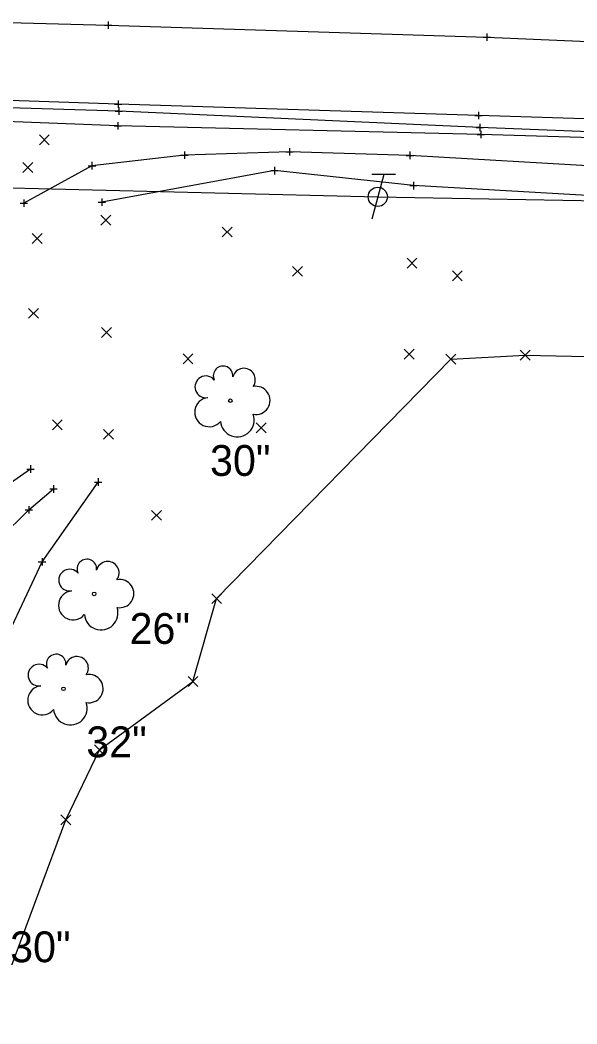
# Model space of a CAD drawing. Extents: x 2005176 to 2005823, y 572472 to 572942.
# Drawn here: x 2005564.6 to 2005639.9, y 572472.3 to 572608.1 of the extents above; entities that cross this region are included whole.
import ezdxf

# ---------------------------------------------------------------- set-up
doc = ezdxf.new("R2010")
doc.units = 0
for name, color, linetype in [('GE_X_Alignment_100_Bearings', 7, 'Continuous'), ('GE_X_Alignment_100_Cardinal_Points', 7, 'Continuous'), ('GE_X_Alignment_100_Distances', 7, 'Continuous'), ('GE_X_Alignment_100_Stations', 7, 'Continuous'), ('GE_X_Alignment_500_Bearings', 7, 'Continuous'), ('GE_X_Alignment_500_Cardinal_Points', 7, 'Continuous'), ('GE_X_Alignment_500_Distances', 7, 'Continuous'), ('SC_Scratch1', 7, 'Continuous'), ('SC_Scratch10', 7, 'Continuous'), ('SC_Scratch8', 7, 'Continuous'), ('SV_P_Mon_Cells_Set', 7, 'Continuous'), ('SV_X_Random_Point', 7, 'Continuous'), ('SV_X_Shot_Marker', 7, 'Continuous'), ('SV_X_Terrain_Boundary', 7, 'Continuous'), ('UT_X_Overhead_Telecom', 7, 'Continuous'), ('VG_X_Text', 7, 'Continuous')]:
    doc.layers.add(name, color=color, linetype=linetype)

msp = doc.modelspace()

# ---------------------------------------------------------------- linework, layer by layer
at = {"layer": 'GE_X_Alignment_100_Bearings'}
msp.add_lwpolyline([(2005818.64, 572588.97), (2005775.2, 572590.4), (2005728.29, 572591.88), (2005676.68, 572593.61), (2005626.55, 572595.19), (2005577.83, 572596.72), (2005526.97, 572598.44), (2005477.01, 572599.53), (2005423.67, 572600.7), (2005368.75, 572601.99), (2005321.74, 572602.99), (2005266.72, 572604.35), (2005220.03, 572605.66)], dxfattribs=at)
at = {"layer": 'GE_X_Alignment_100_Cardinal_Points'}
msp.add_lwpolyline([(2005220.5, 572615.99), (2005272.51, 572614.37), (2005322.2, 572613.2), (2005370.62, 572612.29), (2005424.94, 572611.27), (2005476.5, 572610.17), (2005524.32, 572608.79), (2005576.49, 572607.4), (2005627.69, 572605.77), (2005677.11, 572603.68), (2005728.03, 572601.92), (2005776.18, 572600.5), (2005820.14, 572599.28)], dxfattribs=at)
at = {"layer": 'GE_X_Alignment_100_Distances'}
msp.add_lwpolyline([(2005818.7, 572589.05), (2005775.2, 572590.4), (2005728.29, 572591.88), (2005676.68, 572593.61), (2005626.55, 572595.19), (2005577.83, 572596.72), (2005526.97, 572598.44), (2005477.01, 572599.53), (2005423.67, 572600.7), (2005368.75, 572601.99), (2005321.74, 572602.99), (2005266.72, 572604.35), (2005220.06, 572605.65)], dxfattribs=at)
at = {"layer": 'GE_X_Alignment_100_Stations'}
msp.add_lwpolyline([(2005818.32, 572583.75), (2005776.41, 572584.84), (2005733.38, 572587.41), (2005688.89, 572587.43), (2005643.67, 572588.24), (2005617.3, 572589.8), (2005601, 572590.26), (2005586.78, 572589.84), (2005574.29, 572588.4), (2005565.07, 572583.34)], dxfattribs=at)
at = {"layer": 'GE_X_Alignment_500_Bearings'}
for points in [[(2005565.96, 572547.38), (2005550.47, 572536.53), (2005541.81, 572523.07)], [(2005532.27, 572476.65), (2005533.84, 572485.17), (2005538.2, 572494.97), (2005543.28, 572506.2), (2005549.27, 572518.3), (2005553.94, 572530.22), (2005565.74, 572541.87), (2005569.09, 572544.68)]]:
    msp.add_lwpolyline(points, dxfattribs=at)
at = {"layer": 'GE_X_Alignment_500_Cardinal_Points'}
for points in [[(2005818.94, 572578.27), (2005776.52, 572579.63), (2005733.4, 572581.57), (2005688.76, 572580.93), (2005659.16, 572582.97), (2005643.63, 572584.23), (2005617.78, 572585.7), (2005598.98, 572587.73), (2005575.61, 572583.45)], [(2005556.42, 572509.95), (2005560.7, 572520.33), (2005567.53, 572534.83), (2005575.11, 572545.62)]]:
    msp.add_lwpolyline(points, dxfattribs=at)
at = {"layer": 'GE_X_Alignment_500_Distances'}
msp.add_lwpolyline([(2005220.4, 572616.04), (2005272.51, 572614.37), (2005322.2, 572613.2), (2005370.62, 572612.29), (2005424.94, 572611.27), (2005476.5, 572610.17), (2005524.32, 572608.79), (2005576.49, 572607.4), (2005627.69, 572605.77), (2005677.11, 572603.68), (2005728.03, 572601.92), (2005776.18, 572600.5), (2005820.14, 572599.26)], dxfattribs=at)
at = {"layer": 'SC_Scratch1'}
for p, q in [((2005615.34, 572587.19), (2005612.14, 572587.19)), ((2005613.74, 572587.19), (2005612.14, 572581.19))]:
    msp.add_line(p, q, dxfattribs=at)
msp.add_circle((2005612.94, 572584.19), 1.3, dxfattribs=at)
at = {"layer": 'SC_Scratch10'}
msp.add_lwpolyline([(2005818.55, 572585.94), (2005774.93, 572587.72), (2005728.19, 572589.23), (2005676.71, 572591.12), (2005626.89, 572592.62), (2005577.77, 572593.78), (2005527.62, 572595.75), (2005477.17, 572596.25), (2005467.62, 572596.6)], dxfattribs=at)
at = {"layer": 'SC_Scratch8'}
msp.add_lwpolyline([(2005818.66, 572586.64), (2005775.01, 572588.28), (2005728.16, 572589.79), (2005676.75, 572591.58), (2005626.73, 572593.57), (2005577.92, 572595.76), (2005527.42, 572597.32), (2005476.91, 572598.65), (2005423.43, 572599.27), (2005368.77, 572600.6), (2005321.59, 572601.67), (2005267.03, 572602.73), (2005220.03, 572603.93)], dxfattribs=at)
at = {"layer": 'SV_P_Mon_Cells_Set'}
for p, q in [((2005576.49, 572607.9), (2005576.49, 572606.9)), ((2005576.49, 572607.9), (2005576.49, 572606.9)), ((2005575.99, 572607.4), (2005576.99, 572607.4)), ((2005575.99, 572607.4), (2005576.99, 572607.4)), ((2005576.49, 572607.4), (2005576.49, 572607.4)), ((2005576.49, 572607.4), (2005576.49, 572607.4)), ((2005627.69, 572606.27), (2005627.69, 572605.27)), ((2005627.69, 572606.27), (2005627.69, 572605.27)), ((2005627.19, 572605.77), (2005628.19, 572605.77)), ((2005627.19, 572605.77), (2005628.19, 572605.77)), ((2005627.69, 572605.77), (2005627.69, 572605.77)), ((2005627.69, 572605.77), (2005627.69, 572605.77)), ((2005577.33, 572596.72), (2005578.33, 572596.72)), ((2005577.33, 572596.72), (2005578.33, 572596.72)), ((2005577.83, 572597.22), (2005577.83, 572596.22)), ((2005577.83, 572597.22), (2005577.83, 572596.22)), ((2005577.83, 572596.72), (2005577.83, 572596.72)), ((2005577.83, 572596.72), (2005577.83, 572596.72)), ((2005577.42, 572595.76), (2005578.42, 572595.76)), ((2005577.92, 572596.26), (2005577.92, 572595.26)), ((2005577.92, 572595.76), (2005577.92, 572595.76)), ((2005626.55, 572595.69), (2005626.55, 572594.69)), ((2005626.55, 572595.69), (2005626.55, 572594.69)), ((2005577.77, 572594.28), (2005577.77, 572593.28)), ((2005626.05, 572595.19), (2005627.05, 572595.19)), ((2005626.05, 572595.19), (2005627.05, 572595.19)), ((2005626.55, 572595.19), (2005626.55, 572595.19)), ((2005626.55, 572595.19), (2005626.55, 572595.19)), ((2005626.73, 572594.07), (2005626.73, 572593.07)), ((2005577.27, 572593.78), (2005578.27, 572593.78)), ((2005577.77, 572593.78), (2005577.77, 572593.78)), ((2005626.23, 572593.57), (2005627.23, 572593.57)), ((2005626.39, 572592.62), (2005627.39, 572592.62)), ((2005626.73, 572593.57), (2005626.73, 572593.57)), ((2005626.89, 572593.12), (2005626.89, 572592.12)), ((2005626.89, 572592.62), (2005626.89, 572592.62)), ((2005586.28, 572589.84), (2005587.28, 572589.84)), ((2005586.78, 572590.34), (2005586.78, 572589.34)), ((2005586.78, 572589.84), (2005586.78, 572589.84)), ((2005600.5, 572590.26), (2005601.5, 572590.26)), ((2005601, 572590.76), (2005601, 572589.76)), ((2005601, 572590.26), (2005601, 572590.26)), ((2005617.3, 572590.3), (2005617.3, 572589.3)), ((2005574.29, 572588.9), (2005574.29, 572587.9)), ((2005616.8, 572589.8), (2005617.8, 572589.8)), ((2005617.3, 572589.8), (2005617.3, 572589.8)), ((2005573.79, 572588.4), (2005574.79, 572588.4)), ((2005574.29, 572588.4), (2005574.29, 572588.4)), ((2005598.48, 572587.73), (2005599.48, 572587.73)), ((2005598.98, 572588.23), (2005598.98, 572587.23)), ((2005598.98, 572587.73), (2005598.98, 572587.73)), ((2005617.78, 572586.2), (2005617.78, 572585.2)), ((2005617.28, 572585.7), (2005618.28, 572585.7)), ((2005617.78, 572585.7), (2005617.78, 572585.7)), ((2005564.57, 572583.34), (2005565.57, 572583.34)), ((2005565.07, 572583.84), (2005565.07, 572582.84)), ((2005565.07, 572583.34), (2005565.07, 572583.34)), ((2005575.11, 572583.45), (2005576.11, 572583.45)), ((2005575.61, 572583.95), (2005575.61, 572582.95)), ((2005575.61, 572583.45), (2005575.61, 572583.45)), ((2005565.96, 572547.88), (2005565.96, 572546.88)), ((2005565.46, 572547.38), (2005566.46, 572547.38)), ((2005565.96, 572547.38), (2005565.96, 572547.38)), ((2005569.09, 572545.18), (2005569.09, 572544.18)), ((2005574.61, 572545.62), (2005575.61, 572545.62)), ((2005575.11, 572546.12), (2005575.11, 572545.12)), ((2005575.11, 572545.62), (2005575.11, 572545.62)), ((2005568.59, 572544.68), (2005569.59, 572544.68)), ((2005569.09, 572544.68), (2005569.09, 572544.68)), ((2005565.74, 572542.37), (2005565.74, 572541.37)), ((2005565.24, 572541.87), (2005566.24, 572541.87)), ((2005565.74, 572541.87), (2005565.74, 572541.87)), ((2005567.03, 572534.83), (2005568.03, 572534.83)), ((2005567.53, 572535.33), (2005567.53, 572534.33)), ((2005567.53, 572534.83), (2005567.53, 572534.83))]:
    msp.add_line(p, q, dxfattribs=at)
at = {"layer": 'SV_X_Random_Point'}
for p, q in [((2005567.17, 572591.23), (2005568.51, 572592.57)), ((2005567.17, 572592.57), (2005568.51, 572591.23)), ((2005564.94, 572587.49), (2005566.28, 572588.82)), ((2005564.94, 572588.82), (2005566.28, 572587.49)), ((2005575.49, 572580.35), (2005576.82, 572581.69)), ((2005575.49, 572581.69), (2005576.82, 572580.35)), ((2005566.21, 572577.9), (2005567.54, 572579.24)), ((2005566.21, 572579.24), (2005567.54, 572577.9)), ((2005591.9, 572578.76), (2005593.23, 572580.09)), ((2005591.9, 572580.09), (2005593.23, 572578.76)), ((2005616.9, 572574.55), (2005618.23, 572575.89)), ((2005616.9, 572575.89), (2005618.23, 572574.55)), ((2005601.42, 572573.44), (2005602.76, 572574.77)), ((2005601.42, 572574.77), (2005602.76, 572573.44)), ((2005623.03, 572572.84), (2005624.36, 572574.18)), ((2005623.03, 572574.18), (2005624.36, 572572.84)), ((2005565.71, 572567.76), (2005567.04, 572569.1)), ((2005565.71, 572569.1), (2005567.04, 572567.76)), ((2005575.57, 572565.18), (2005576.91, 572566.51)), ((2005575.57, 572566.51), (2005576.91, 572565.18)), ((2005586.6, 572561.61), (2005587.93, 572562.94)), ((2005586.6, 572562.94), (2005587.93, 572561.61)), ((2005616.53, 572562.25), (2005617.87, 572563.58)), ((2005616.53, 572563.58), (2005617.87, 572562.25)), ((2005622.16, 572561.55), (2005623.49, 572562.89)), ((2005622.16, 572562.89), (2005623.49, 572561.55)), ((2005632.21, 572562.09), (2005633.54, 572563.43)), ((2005632.21, 572563.43), (2005633.54, 572562.09)), ((2005568.93, 572552.7), (2005570.26, 572554.03)), ((2005568.93, 572554.03), (2005570.26, 572552.7)), ((2005596.51, 572552.29), (2005597.85, 572553.62)), ((2005596.51, 572553.62), (2005597.85, 572552.29)), ((2005575.86, 572551.4), (2005577.19, 572552.73)), ((2005575.86, 572552.73), (2005577.19, 572551.4)), ((2005582.36, 572540.45), (2005583.69, 572541.78)), ((2005582.36, 572541.78), (2005583.69, 572540.45)), ((2005590.48, 572529.19), (2005591.81, 572530.52)), ((2005590.48, 572530.52), (2005591.81, 572529.19)), ((2005587.28, 572517.97), (2005588.62, 572519.31)), ((2005587.28, 572519.31), (2005588.62, 572517.97)), ((2005574.62, 572508.73), (2005575.95, 572510.07)), ((2005574.62, 572510.07), (2005575.95, 572508.73)), ((2005570.09, 572499.28), (2005571.43, 572500.62)), ((2005570.09, 572500.62), (2005571.43, 572499.28))]:
    msp.add_line(p, q, dxfattribs=at)
at = {"layer": 'SV_X_Shot_Marker'}
for centre in [(2005593, 572556.62), (2005574.58, 572530.49), (2005570.43, 572517.65)]:
    msp.add_circle(centre, 0.24, dxfattribs=at)
for centre, radius, start, end in [((2005592.02, 572559.99), 1.32, 354.0047, 205.9741), ((2005594.83, 572559.45), 1.55, 323.83, 165.0376), ((2005589.69, 572558.49), 1.47, 39.0625, 279.5412), ((2005596.46, 572556.66), 1.91, 259.1453, 101.4596), ((2005590.15, 572555.07), 1.97, 96.1722, 320.5737), ((2005593.95, 572554.02), 2.28, 184.9476, 19.4572), ((2005573.6, 572533.86), 1.32, 354.0047, 205.9741), ((2005576.41, 572533.32), 1.55, 323.83, 165.0376), ((2005571.27, 572532.36), 1.47, 39.0625, 279.5412), ((2005578.04, 572530.53), 1.91, 259.1453, 101.4596), ((2005571.73, 572528.94), 1.97, 96.1722, 320.5737), ((2005575.53, 572527.89), 2.28, 184.9476, 19.4572), ((2005569.44, 572521.01), 1.32, 354.0047, 205.9741), ((2005572.25, 572520.47), 1.55, 323.83, 165.0376), ((2005567.12, 572519.51), 1.47, 39.0625, 279.5412), ((2005573.89, 572517.68), 1.91, 259.1453, 101.4596), ((2005567.57, 572516.1), 1.97, 96.1722, 320.5737), ((2005571.37, 572515.04), 2.28, 184.9476, 19.4572)]:
    msp.add_arc(centre, radius, start, end, dxfattribs=at)
at = {"layer": 'SV_X_Terrain_Boundary'}
msp.add_lwpolyline([(2005414.7, 572571.99), (2005458.48, 572515.56), (2005472.63, 572507.15), (2005476.65, 572499.23), (2005498.18, 572493.71), (2005500.59, 572492.24), (2005514.67, 572482.57), (2005521.37, 572479.61), (2005532.27, 572476.65), (2005543.24, 572472.34), (2005552.27, 572478.11), (2005563.46, 572480.3), (2005570.76, 572499.94), (2005575.29, 572509.4), (2005587.95, 572518.64), (2005591.14, 572529.85), (2005622.83, 572562.22), (2005632.87, 572562.76), (2005676.67, 572561.82)], dxfattribs=at)
at = {"layer": 'UT_X_Overhead_Telecom'}
for p, q in [((2005468.84, 572587.72), (2005612.94, 572584.19)), ((2005612.94, 572584.19), (2005774.39, 572581.34))]:
    msp.add_line(p, q, dxfattribs=at)

# ---------------------------------------------------------------- texts
at = {"layer": 'VG_X_Text'}
for s, p in [('30"', (2005590.26, 572546.45)), ('26"', (2005579.37, 572523.73)), ('32"', (2005573.52, 572508.4)), ('30"', (2005563.22, 572480.68))]:
    msp.add_text(s, height=4.167, dxfattribs=at).set_placement(p)

doc.saveas('drawing.dxf')
